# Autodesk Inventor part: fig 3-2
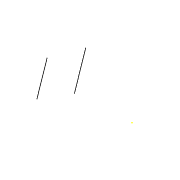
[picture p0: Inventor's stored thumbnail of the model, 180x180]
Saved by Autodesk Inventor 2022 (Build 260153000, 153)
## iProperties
Created: 2011-07
Part Number: fig 3-2
Material: Generic
Document SubType Name: Modeling
Designer: CadCim
Density: 1 g/cm^3
Appearance: Default
Author: CadCim
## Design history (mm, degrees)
sketch "Sketch1"
  geometry: L1 (-29, 4)-(-20, -8); L2 (-16, -0.965)-(-25.943, 12.292); 1 further point
  constraints: 4 end point, 1 parallel, 1 other
